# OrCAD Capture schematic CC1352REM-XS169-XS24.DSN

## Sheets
1 Mechanical: size A4; title: CC1352REM-XS169-XS24; rev: C0
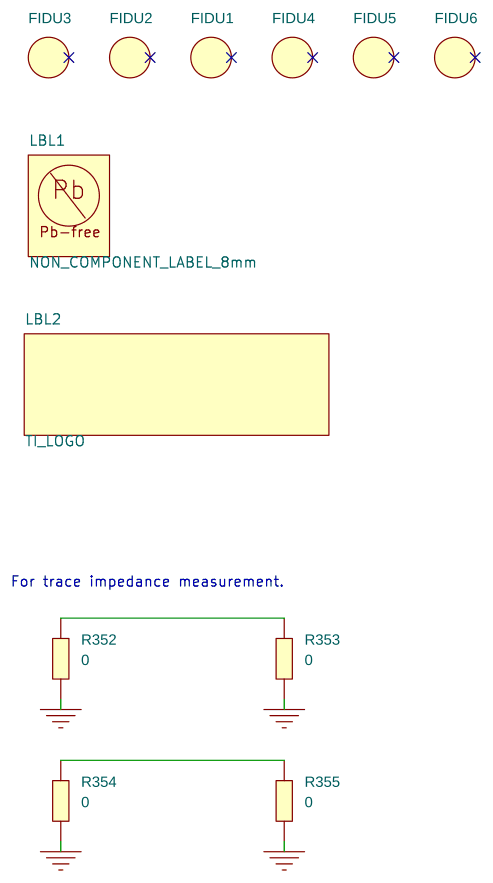
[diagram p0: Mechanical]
2 CC1352REM-XS169-XS24: size A3
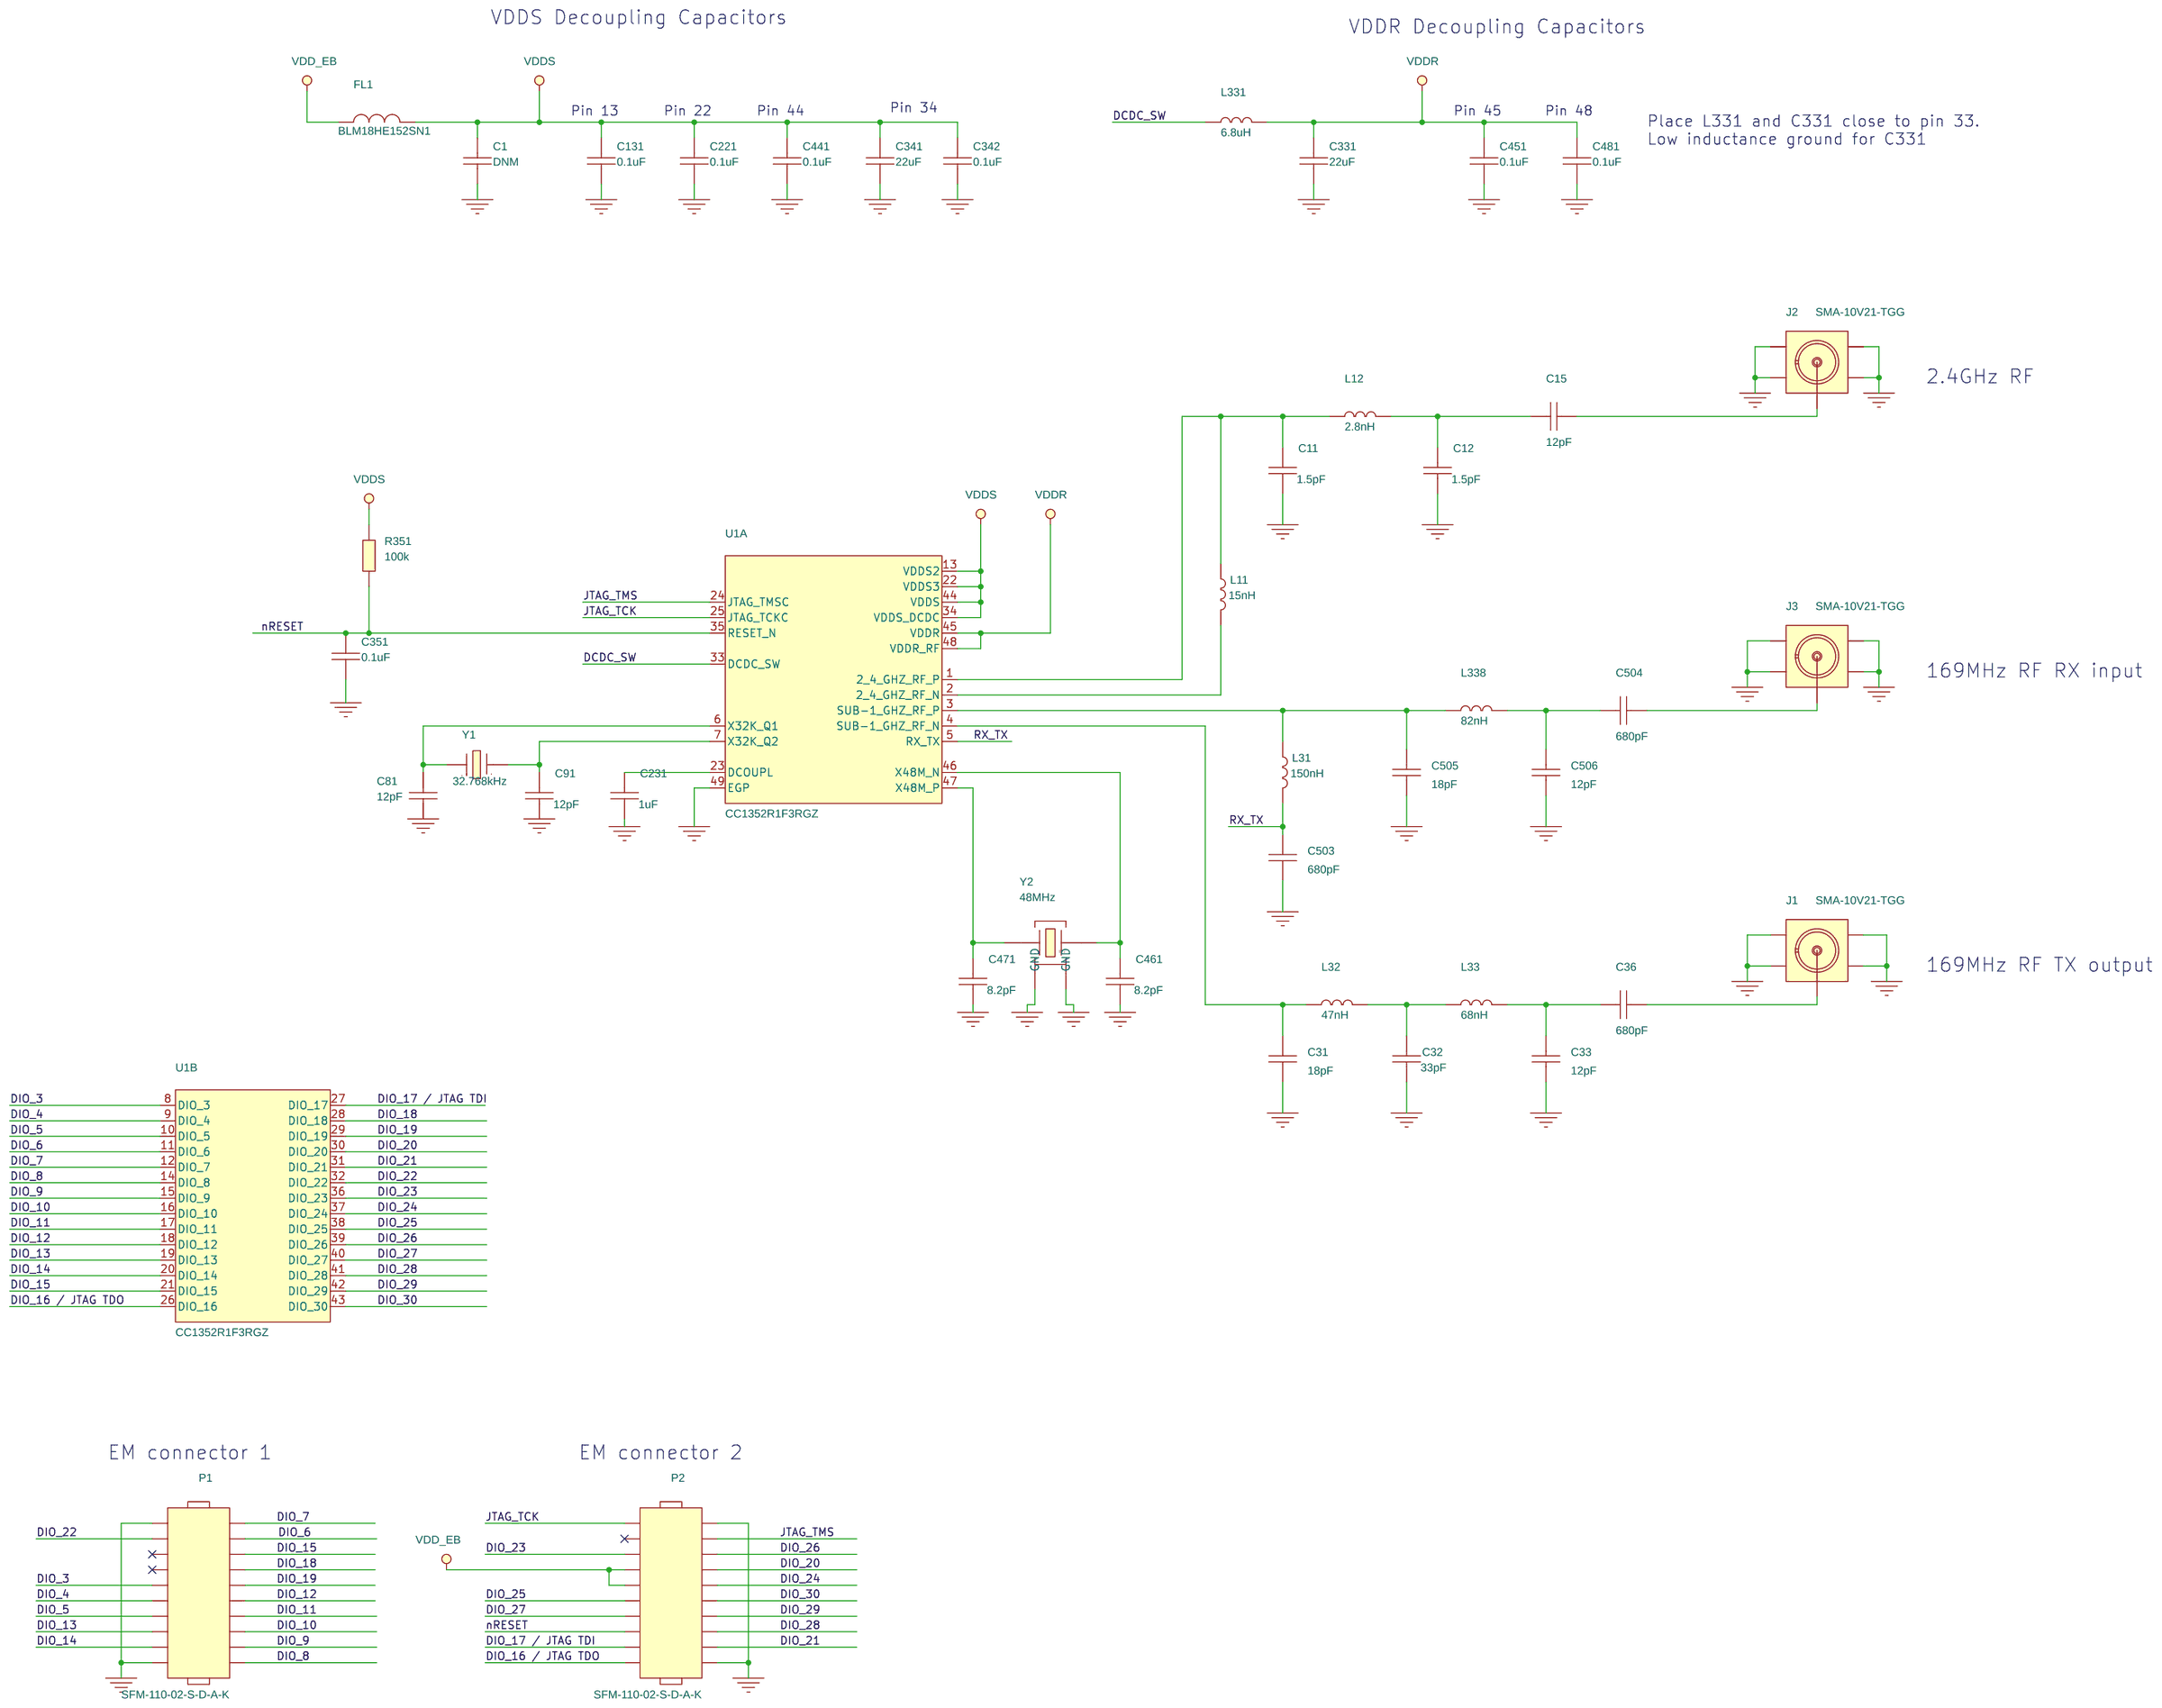
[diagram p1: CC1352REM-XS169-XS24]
3 Revision
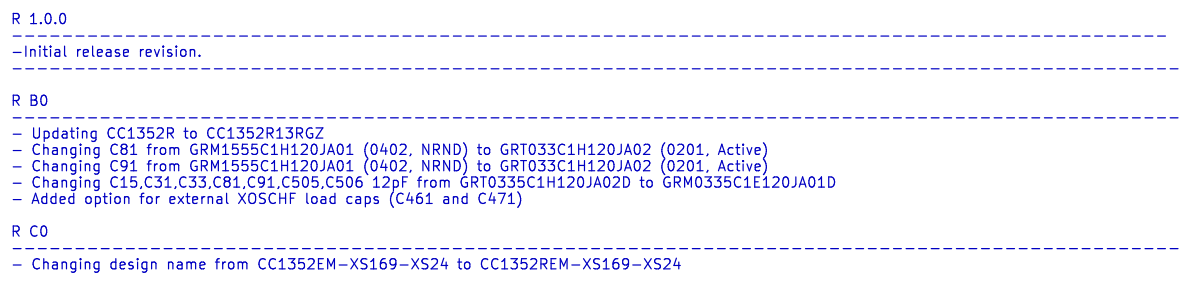
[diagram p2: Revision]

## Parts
sheet CC1352REM-XS169-XS24
C1  DNM  [CAPC1608X90A2N]
C11  1.5pF  [CAPC0603X35B2N]
C12  1.5pF  [CAPC0603X35B2N]
C15  12pF  [CAPC0603X35B2N]
C31  18pF  [CAPC0603X35B2N]
C32  33pF  [CAPC0603X35B2N]
C33  12pF  [CAPC0603X35B2N]
C36  680pF  [CAPC0603X35B2N]
C81  12pF  [CAPC0603X35B2N]
C91  12pF  [CAPC0603X35B2N]
C131  0.1uF  [CAPC1005X60B2N]
C221  0.1uF  [CAPC1005X60B2N]
C231  1uF  [CAPC1005X60A2N]
C331  22uF  [CAPC1608X100A2N]
C341  22uF  [CAPC1608X100A2N]
C342  0.1uF  [CAPC1005X60B2N]
C351  0.1uF  [CAPC1005X60B2N]
C441  0.1uF  [CAPC1005X60B2N]
C451  0.1uF  [CAPC1005X60B2N]
C461  8.2pF  [CAPC0603X35B2N]
C471  8.2pF  [CAPC0603X35B2N]
C481  0.1uF  [CAPC1005X60B2N]
C503  680pF  [CAPC0603X35B2N]
C504  680pF  [CAPC0603X35B2N]
C505  18pF  [CAPC0603X35B2N]
C506  12pF  [CAPC0603X35B2N]
FL1  BLM18HE152SN1  [FIL_BLM18HE152SN1DN]
J1  SMA-10V21-TGG  [HUSTSAN_SMA10V21TGGAN]
J2  SMA-10V21-TGG  [HUSTSAN_SMA10V21TGGAN]
J3  SMA-10V21-TGG  [HUSTSAN_SMA10V21TGGAN]
L11  15nH  [INDC0603X33A2N]
L12  2.8nH  [INDC0603X33A2N]
L31  150nH  [INDC0603X33A2N]
L32  47nH  [INDC1005X60B2N]
L33  68nH  [INDC1005X60A2N]
L331  6.8uH  [INDC2012X150A2N]
L338  82nH  [INDC1005X60A2N]
P1  SFM-110-02-S-D-A-K  [SAMTEC_SFM11002AN]
P2  SFM-110-02-S-D-A-K  [SAMTEC_SFM11002AN]
R351  100k  [RESC1005X40B2N]
U1  CC1352R1F3RGZ  [QFNFC50P700X700X100-49A2N]  (sections A,B)
Y1  32.768kHz  [XTAL_FC135_A2N]
Y2  48MHz  [OSCCC200X160X50-4B2N]
sheet Mechanical
FIDU1  FIDU_1MM  [FID100X115B]
FIDU2  FIDU_1MM  [FID100X115B]
FIDU3  FIDU_1MM  [FID100X115B]
FIDU4  FIDU_1MM  [FID100X115B]
FIDU5  FIDU_1MM  [FID100X115B]
FIDU6  FIDU_1MM  [FID100X115B]
LBL1  NON_COMPONENT_LABEL_8mm  [LABEL_PB-FREE_8MM_A2N]
LBL2  TI_LOGO  [TI_LOGO_1]
R352  0  [RESC0603X35B2N]
R353  0  [RESC0603X35B2N]
R354  0  [RESC0603X35B2N]
R355  0  [RESC0603X35B2N]

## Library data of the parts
C1 = CAPACITOR: CAPACITOR, CERAMIC, TBD, 0603, SMD, DNM; ALT_SYMBOLS: CAPC1608X90A2L,CAPC1608X90A2M; Additional Datasheet URL: N/A; AutoDoc File: https://notefied-dynamic-precision.com/DB/Apps/Desktop/Item/Object.aspx?id=50475; BU Name: DYNAMIC PRECISION GDANSK; Client Status: RELEASED; Country of Origin: Missing Info; Datasheet URL: N/A; Datasheet URL 1: N/A; Datasheet URL 2: N/A; Mass: N/A; Max Oper Temp: N/A; Maximum Operating Temperature: N/A; Min Oper Temp: N/A; Minimum Operating Temperature: N/A; Mounting Type: SMD; NOTEfied URL: https://notefied-dynamic-precision.com/NOTEfiedWebInterface/part/show?partNumber=02-01324; Old Footprint: CAPC1608X90N,0603; PCB Package: 0603; Packing Size: N/A; Packing Type: Missing Info; Part Number: 02-01324; Part Type: Capacitor|CERAMIC|0603|STANDARD; ROHS: Compliant; Revision: R024; RoHS Status: ROHS_COMPLIANT; Status: Released; Type: Capacitor; Vendor: MANUFACTURER SELECTION; Vendor Part Number: CAPACITOR_TBD_0603_DNM; Vendor Part Status: Active; Weight: N/A
C11 C12 = CAPACITOR: CAPACITOR, CERAMIC C0G/NP0, 1.5pF, 50V, -0.1pF/+0.1pF, -55DEGC/+125DEGC, 0201, SMD; ALT_SYMBOLS: CAPC0603X35B2L,CAPC0603X35B2M; Additional Datasheet URL: https://search.murata.co.jp/Ceramy/image/img/A01X/G101/ENG/GRM0335C1H1R5BA01-01A.pdf; Budgetary Price: 0.00272 USD; Country of Origin: Missing Info; Datasheet URL: https://www.murata.com/-/media/webrenewal/support/library/catalog/products/capacitor/mlcc/c02e.ashx?la=en-gb; Dielectric Type: C0G/NP0; Lead Time: 11; Mass: 0.00033g; Maximum Operating Temperature: +125DEGC; Maximum Tolerance: +0.1pF; Minimum Operating Temperature: -55DEGC; Minimum Tolerance: -0.1pF; Mounting Type: SMD; NOTEfied URL: https://notefied-dynamic-precision.com/NOTEfiedWebInterface/part/show?partNumber=02-06129; PCB Package: 0201; Packing Size: 50000; Packing Type: Tape & Reel; Part Number: 02-06129; Part Type: Capacitor|CERAMIC|0201|STANDARD; REACH/SVHC Compliance: Compliant; REACH/SVHC Details: SVHC List Version Jul 7, 2017; REACH/SVHC Source: REACH Declaration; REACH/SVHC Status: Unaffected; ROHS: Compliant; Rated Voltage: 50V; Revision: R020; Status: Released; Texas Part Status: Under Review; Type: Capacitor; Vendor: MURATA; Vendor Part Number: GRM0335C1H1R5BA01J; Vendor Part Status: Active
C15 C33 C506 = CAPACITOR: CAPACITOR, CERAMIC C0G/NP0, 12pF, 25V, -5%/+5%, -55DEGC/+125DEGC, 0201, SMD; ALT_SYMBOLS: CAPC0603X35B2L,CAPC0603X35B2M; Additional Datasheet URL: https://www.murata.com/-/media/webrenewal/support/library/catalog/products/capacitor/mlcc/c02e.ashx?la=en-gb; Datasheet URL: https://search.murata.co.jp/Ceramy/image/img/A01X/G101/ENG/GRM0335C1E120JA01-01A.pdf; Dielectric Type: C0G/NP0; Mass: 0.00033g; Maximum Operating Temperature: +125DEGC; Maximum Tolerance: +5%; Minimum Operating Temperature: -55DEGC; Minimum Tolerance: -5%; Mounting Type: SMD; NOTEfied URL: https://notefied-dynamic-precision.com/NOTEfiedWebInterface/part/show?partNumber=02-09489; PCB Package: 0201; Packing Size: 15000; Packing Type: Tape & Reel; Part Number: 02-09489; Part Type: Capacitor|CERAMIC|0201|STANDARD; REACH/SVHC Compliance: Compliant; REACH/SVHC Details: SVHC List Version Jul 16, 2019; REACH/SVHC Source: REACH Declaration; REACH/SVHC Status: Unaffected; ROHS: Compliant; Rated Voltage: 25V; Revision: R001; Status: Released; Texas Part Status: Under Review; Type: Capacitor; Vendor: MURATA; Vendor Part Number: GRM0335C1E120JA01D; Vendor Part Status: Active
C31 C505 = CAPACITOR: CAPACITOR, CERAMIC C0G/NP0, 18pF, 25V, -5%/+5%, -55DEGC/+125DEGC, 0201, SMD; ALT_SYMBOLS: CAPC0603X35B2L,CAPC0603X35B2M; Additional Datasheet URL: https://search.murata.co.jp/Ceramy/image/img/A01X/G101/ENG/GRM0335C1E180JA01-01A.pdf; Budgetary Price: 0.0024 USD; Datasheet URL: https://www.murata.com/-/media/webrenewal/support/library/catalog/products/capacitor/mlcc/c02e.ashx?la=en-gb; Dielectric Type: C0G/NP0; Lead Time: 11; Mass: 0.00033g; Maximum Operating Temperature: +125DEGC; Maximum Tolerance: +5%; Minimum Operating Temperature: -55DEGC; Minimum Tolerance: -5%; Mounting Type: SMD; NOTEfied URL: https://notefied-dynamic-precision.com/NOTEfiedWebInterface/part/show?partNumber=02-09247; PCB Package: 0201; Packing Size: 15000; Packing Type: Tape & Reel; Part Number: 02-09247; Part Type: Capacitor|CERAMIC|0201|STANDARD; REACH/SVHC Compliance: Compliant; REACH/SVHC Details: SVHC List Version Jan 16, 2020; REACH/SVHC Source: REACH Declaration; REACH/SVHC Status: Unaffected; ROHS: Compliant; Rated Voltage: 25V; Revision: R004; Status: Released; Texas Part Status: Under Review; Type: Capacitor; Vendor: MURATA; Vendor Part Number: GRM0335C1E180JA01D; Vendor Part Status: Active
C32 = CAPACITOR: CAPACITOR, CERAMIC, C0G/NP0, 33pF, 25V, -5%/+5%, -55DEGC/+125DEGC, 0201, SMD; ALT_SYMBOLS: CAPC0603X35B2L,CAPC0603X35B2M; Additional Datasheet URL: https://search.murata.co.jp/Ceramy/image/img/A01X/G101/ENG/GRM0335C1E330JA01-01A.pdf; Budgetary Price: 0.0024 USD; Datasheet URL: https://www.murata.com/-/media/webrenewal/support/library/catalog/products/capacitor/mlcc/c02e.ashx?la=en-gb; Dielectric Type: C0G/NP0; Lead Time: 11; Mass: 0.00033g; Maximum Operating Temperature: +125DEGC; Maximum Tolerance: +5%; Minimum Operating Temperature: -55DEGC; Minimum Tolerance: -5%; Mounting Type: SMD; NOTEfied URL: https://notefied-dynamic-precision.com/NOTEfiedWebInterface/part/show?partNumber=02-08392; PCB Package: 0201; Packing Size: 15000; Packing Type: Tape & Reel; Part Number: 02-08392; Part Type: Capacitor|CERAMIC|0201|STANDARD; ROHS: Compliant; Rated Voltage: 25V; Revision: R005; Status: Released; Type: Capacitor; Vendor: MURATA; Vendor Part Number: GRM0335C1E330JA01D; Vendor Part Status: Active
C36 C503 C504 = CAPACITOR: CAPACITOR, CERAMIC, C0G/NP0, 680pF, 25V, -5%/+5%, -55DEGC/+125DEGC, 0201, SMD; ALT_SYMBOLS: CAPC0603X35B2L,CAPC0603X35B2M; Additional Datasheet URL: https://search.murata.co.jp/Ceramy/image/img/A01X/G101/ENG/GRM0335C1E681JA01-01A.pdf; Datasheet URL: https://www.murata.com/-/media/webrenewal/support/library/catalog/products/capacitor/mlcc/c02e.ashx?la=en-gb; Dielectric Type: C0G/NP0; Mass: 0.00033g; Maximum Operating Temperature: +125DEGC; Maximum Tolerance: +5%; Minimum Operating Temperature: -55DEGC; Minimum Tolerance: -5%; Mounting Type: SMD; NOTEfied URL: https://notefied-dynamic-precision.com/NOTEfiedWebInterface/part/show?partNumber=02-09578; PCB Package: 0201; Packing Size: 15000; Packing Type: Tape & Reel; Part Number: 02-09578; Part Type: Capacitor|CERAMIC|0201|STANDARD; REACH/SVHC Compliance: Compliant; REACH/SVHC Details: SVHC List Version Jan 16, 2020; REACH/SVHC Source: REACH Declaration; REACH/SVHC Status: Unaffected; ROHS: Compliant; Rated Voltage: 25V; Revision: R001; Status: Released; Texas Part Status: Under Review; Type: Capacitor; Vendor: MURATA; Vendor Part Number: GRM0335C1E681JA01D; Vendor Part Status: Active
C81 = CAPACITOR: CAPACITOR, CERAMIC C0G/NP0, 12pF, 25V, -5%/+5%, -55DEGC/+125DEGC, 0201, SMD; ALT_SYMBOLS: CAPC0603X35B2L,CAPC0603X35B2M; Additional Datasheet URL: https://www.murata.com/-/media/webrenewal/support/library/catalog/products/capacitor/mlcc/c02e.ashx?la=en-gb; AutoDoc File: https://notefied-dynamic-precision.com/DB/Apps/Desktop/Item/Object.aspx?id=113345; BU Name: TEXAS INSTRUMENTS NORWAY; Budget Currency: EUR; Budget Price: 0.007; Datasheet URL: https://search.murata.co.jp/Ceramy/image/img/A01X/G101/ENG/GRM0335C1E120JA01-01A.pdf; Datasheet URL 1: http://psearch.murata.com/capacitor/product/GRM1555C1H120JA01%23.pdf; Datasheet URL 2: http://search.murata.co.jp/Ceramy/image/img/w_hinm/L0005E.pdf; Definied Quality: INDUSTRIAL; Dielectric Type: C0G/NP0; Esd Level: N/A; MPN: GRM1555C1H120JA01D; MPN Status: ACTIVE; MSL: 1; MTBF: N/A; MTBF Standard: N/A; Manufacturer: MURATA; Mass: 0.00033g; Max Oper Temp: +125DEGC; Max Tol: +5%; Maximum Operating Temperature: +125DEGC; Maximum Tolerance: +5%; Min Oper Temp: -55DEGC; Min Tol: -5%; Minimum Operating Temperature: -55DEGC; Minimum Tolerance: -5%; Mounting Type: SMD; NOTE Status: PREFERRED; NOTEfied URL: https://notefied-dynamic-precision.com/NOTEfiedWebInterface/part/show?partNumber=02-09489; Old Footprint: CAPC1005X60N; PCB Package: 0201; Packing Size: 15000; Packing Type: Tape & Reel; Part Number: 02-09489; Part Type: Capacitor|CERAMIC|0201|STANDARD; REACH/SVHC Compliance: Compliant; REACH/SVHC Details: SVHC List Version Jul 16, 2019; REACH/SVHC Source: REACH Declaration; REACH/SVHC Status: Unaffected; REACH/SVHC_COMPLIANCE: COMPLIANT; REACH/SVHC_DETAILS: SVHC LIST VERSION Dec 17, 2015; REACH/SVHC_SOURCE: REACH DECLARATION; REACH/SVHC_STATUS: UNAFFECTED; ROHS: Compliant; Rated Voltage: 25V; Revision: R001; RoHS Status: ROHS_COMPLIANT; Rtd Voltage: 50V; Status: Released; Texas Part Status: Under Review; Type: Capacitor; Vendor: MURATA; Vendor Part Number: GRM0335C1E120JA01D; Vendor Part Status: Active; WEIGHT: 0.0016g
C91 = CAPACITOR: CAPACITOR, CERAMIC C0G/NP0, 12pF, 25V, -5%/+5%, -55DEGC/+125DEGC, 0201, SMD; ALT_SYMBOLS: CAPC0603X35B2L,CAPC0603X35B2M; Additional Datasheet URL: https://www.murata.com/-/media/webrenewal/support/library/catalog/products/capacitor/mlcc/c02e.ashx?la=en-gb; AutoDoc File: https://notefied-dynamic-precision.com/DB/Apps/Desktop/Item/Object.aspx?id=114571; BU Name: TEXAS INSTRUMENTS NORWAY; Budget Currency: EUR; Budget Price: 0.006; Client Status: UNDER_REVIEW; Datasheet URL: https://search.murata.co.jp/Ceramy/image/img/A01X/G101/ENG/GRM0335C1E120JA01-01A.pdf; Datasheet URL 1: http://psearch.murata.com/capacitor/product/GRM1555C1H150JA01%23.pdf; Datasheet URL 2: http://psearch.en.murata.com/capacitor/product/GRM1555C1H150JA01%23.html; Definied Quality: INDUSTRIAL; Dielectric Type: C0G/NP0; Esd Level: N/A; LifeCycle Status: ACTIVE; MPN: CAPACITOR_0402_12pF_C0G/NP0_M_+/-5%_50V; MPN Status: ACTIVE; MSL: N/A; MTBF: N/A; MTBF Standard: N/A; Manufacturer: MANUFACTURER SELECTION; Mass: 0.00033g; Max Oper Temp: +125DEGC; Max Tol: +5%; Maximum Operating Temperature: +125DEGC; Maximum Tolerance: +5%; Min Oper Temp: -55DEGC; Min Tol: -5%; Minimum Operating Temperature: -55DEGC; Minimum Tolerance: -5%; Mounting Type: SMD; NOTE Status: PREFERRED; NOTEfied URL: https://notefied-dynamic-precision.com/NOTEfiedWebInterface/part/show?partNumber=02-09489; Old Footprint: CAPC1005X60N; PCB Package: 0201; Packing Size: 15000; Packing Type: Tape & Reel; Part Number: 02-09489; Part Type: Capacitor|CERAMIC|0201|STANDARD; REACH/SVHC Compliance: Compliant; REACH/SVHC Details: SVHC List Version Jul 16, 2019; REACH/SVHC Source: REACH Declaration; REACH/SVHC Status: Unaffected; REACH/SVHC_COMPLIANCE: COMPLIANT; REACH/SVHC_DETAILS: SVHC List Version Jan 12, 2017; REACH/SVHC_SOURCE: REACH DECLARATION; REACH/SVHC_STATUS: UNAFFECTED; ROHS: Compliant; Rated Voltage: 25V; Revision: R001; RoHS Status: ROHS_COMPLIANT; Rtd Voltage: 50V; Status: Released; Texas Part Status: Under Review; Type: Capacitor; Vendor: MURATA; Vendor Part Number: GRM0335C1E120JA01D; Vendor Part Status: Active; WEIGHT: 0.0016g
C131 C221 C351 C441 C451 C481 = CAPACITOR: CAPACITOR, CERAMIC X7R, 0.1uF, 25V, -10%/+10%, -55DEGC/+125DEGC, 0402, SMD; Additional Datasheet URL: https://search.murata.co.jp/Ceramy/image/img/A01X/G101/ENG/GRM155R71E104KE14-01A.pdf; AutoDoc File: https://notefied-dynamic-precision.com/DB/Apps/Desktop/Item/Object.aspx?id=115293; BU Name: TEXAS INSTRUMENTS NORWAY; Budgetary Price: 0.00567 USD; Client Status: UNDER_REVIEW; Datasheet URL: https://www.murata.com/-/media/webrenewal/support/library/catalog/products/capacitor/mlcc/c02e.ashx?la=en-gb; Datasheet URL 1: http://psearch.en.murata.com/capacitor/product/GRM155R71E104KE14%23.pdf; Datasheet URL 2: http://search.murata.co.jp/Ceramy/image/img/w_hinm/L0005E.pdf; Dielectric Type: X7R; Lead Time: 11; LifeCycle Status: ACTIVE; MPN: GRM155R70J104KA01D; MPN Status: ACTIVE; Manufacturer: MURATA; Mass: 0.0016g; Max Oper Temp: +125DEGC; Max Tol: +10%; Maximum Operating Temperature: +125DEGC; Maximum Tolerance: +10%; Min Oper Temp: -55DEGC; Min Tol: -10%; Minimum Operating Temperature: -55DEGC; Minimum Tolerance: -10%; Mounting Type: SMD; NOTE Status: PREFERRED; NOTEfied URL: https://notefied-dynamic-precision.com/NOTEfiedWebInterface/part/show?partNumber=02-07861; Old Footprint: CAPC1005X60N,0402; PCB Package: 0402; Packing Size: 10000; Packing Type: Tape & Reel; Part Number: 02-07861; Part Type: Capacitor|CERAMIC|0402|STANDARD; REACH/SVHC Compliance: Compliant; REACH/SVHC Details: SVHC List Version Jul 7, 2017; REACH/SVHC Source: REACH Declaration; REACH/SVHC Status: Unaffected; REACH/SVHC_COMPLIANCE: COMPLIANT; REACH/SVHC_DETAILS: SVHC LIST VERSION Jun 20, 2016; REACH/SVHC_SOURCE: REACH DECLARATION; REACH/SVHC_STATUS: UNAFFECTED; ROHS: Compliant; Rated Voltage: 25V; Revision: R017; RoHS Status: ROHS_COMPLIANT; Rtd Voltage: 25V; Status: Released; Texas Part Status: Under Review; Type: Capacitor; Vendor: MURATA; Vendor Part Number: GRM155R71E104KE14D; Vendor Part Status: Active; WEIGHT: 0.0016g
C231 = CAPACITOR: CAPACITOR, CERAMIC X5R, 1uF, 25V, -10%/+10%, -55DEGC/+85DEGC, 0402, SMD; ALT_SYMBOLS: CAPC1005X60A2L,CAPC1005X60A2M; Additional Datasheet URL: https://search.murata.co.jp/Ceramy/image/img/A01X/G101/ENG/GRM155R61E105KA12-01A.pdf; Budgetary Price: 0.01386 USD; Country of Origin: China,Philippines; Datasheet URL: https://www.murata.com/-/media/webrenewal/support/library/catalog/products/capacitor/mlcc/c02e.ashx?la=en-gb; Dielectric Type: X5R; FPLIST: CAPC1005X60A2N,CAPC1005X60B2N; Lead Time: 11; Mass: 0.0016g; Maximum Operating Temperature: +85DEGC; Maximum Tolerance: +10%; Minimum Operating Temperature: -55DEGC; Minimum Tolerance: -10%; Mounting Type: SMD; NOTEfied URL: https://notefied-dynamic-precision.com/NOTEfiedWebInterface/part/show?partNumber=02-07864; PCB Package: 0402; Packing Size: 10000; Packing Type: Tape & Reel; Part Number: 02-07864; Part Type: Capacitor|CERAMIC|0402|STANDARD; REACH/SVHC Compliance: Compliant; REACH/SVHC Details: SVHC List Version Jan 15, 2018; REACH/SVHC Source: REACH Declaration; REACH/SVHC Status: Unaffected; ROHS: Compliant; Rated Voltage: 25V; Revision: R024; Status: Released; Texas Part Status: Under Review; Type: Capacitor; Vendor: MURATA; Vendor Part Number: GRM155R61E105KA12D; Vendor Part Status: Active
C331 C341 = CAPACITOR: CAPACITOR, CERAMIC, X5R, 22uF, 6.3V, -20%/+20%, -55DEGC/+85DEGC, 0603, SMD; ALT_SYMBOLS: CAPC1608X100A2L,CAPC1608X100A2M; Additional Datasheet URL: https://search.murata.co.jp/Ceramy/image/img/A01X/G101/ENG/GRM188R60J226MEA0-01A.pdf; AutoDoc File: https://notefied-dynamic-precision.com/DB/Apps/Desktop/Item/Object.aspx?id=104385; BU Name: DYNAMIC PRECISION GDANSK; Budget Currency: EUR; Budget Price: 0.062; Budgetary Price: 0.04731 USD; Client Status: UNDER_REVIEW; Country of Origin: Japan; Datasheet URL: https://www.murata.com/-/media/webrenewal/support/library/catalog/products/capacitor/mlcc/c02e.ashx?la=en-gb; Datasheet URL 1: http://psearch.murata.com/capacitor/product/GRM188R60J226MEA0%23.pdf; Datasheet URL 2: http://search.murata.co.jp/Ceramy/image/img/w_hinm/L0005E.pdf; Definied Quality: INDUSTRIAL; Dielectric Type: X5R; Esd Level: N/A; Lead Time: 11; LifeCycle Status: ACTIVE; MPN: GRM188R60J226MEA0D; MPN Status: ACTIVE; Manufacturer: MURATA; Mass: 0.0091g; Max Oper Temp: +85DEGC; Max Tol: +20%; Maximum Operating Temperature: +85DEGC; Maximum Tolerance: +20%; Min Oper Temp: -55DEGC; Min Tol: -20%; Minimum Operating Temperature: -55DEGC; Minimum Tolerance: -20%; Mounting Type: SMD; NOTE Status: PREFERRED; NOTEfied URL: https://notefied-dynamic-precision.com/NOTEfiedWebInterface/part/show?partNumber=02-07053; PCB Package: 0603; Packing Size: 4000; Packing Type: Tape & Reel; Part Number: 02-07053; Part Type: Capacitor|CERAMIC|0603|STANDARD; REACH/SVHC Compliance: Compliant; REACH/SVHC Details: SVHC List Version Jul 7, 2017; REACH/SVHC Source: REACH Declaration; REACH/SVHC Status: Unaffected; REACH/SVHC_COMPLIANCE: COMPLIANT; REACH/SVHC_DETAILS: SVHC LIST VERSION Dec 17, 2015; REACH/SVHC_SOURCE: REACH DECLARATION; REACH/SVHC_STATUS: UNAFFECTED; ROHS: Compliant; Rated Voltage: 6.3V; Revision: R018; RoHS Status: ROHS_COMPLIANT; Rtd Voltage: 6.3V; Status: Released; Texas Part Status: Under Review; Type: Capacitor; Vendor: MURATA; Vendor Part Number: GRM188R60J226MEA0D; Vendor Part Status: Active; WEIGHT: 0.0091g
C342 = CAPACITOR: CAPACITOR, CERAMIC X7R, 0.1uF, 25V, -10%/+10%, -55DEGC/+125DEGC, 0402, SMD; Additional Datasheet URL: https://search.murata.co.jp/Ceramy/image/img/A01X/G101/ENG/GRM155R71E104KE14-01A.pdf; AutoDoc File: https://notefied-dynamic-precision.com/DB/Apps/Desktop/Item/Object.aspx?id=115293; BU Name: TEXAS INSTRUMENTS NORWAY; Budgetary Price: 0.00567 USD; Cage Code: C0151; Client Status: UNDER_REVIEW; Datasheet URL: https://www.murata.com/-/media/webrenewal/support/library/catalog/products/capacitor/mlcc/c02e.ashx?la=en-gb; Datasheet URL 1: http://psearch.en.murata.com/capacitor/product/GRM155R71E104KE14%23.pdf; Datasheet URL 2: http://search.murata.co.jp/Ceramy/image/img/w_hinm/L0005E.pdf; Definied Quality: INDUSTRIAL; Dielectric Type: X7R; Esd Level: N/A; Lead Time: 11; MPN: GRM188R71E104KA01D; MPN Status: NRND; MSL: 1; MTBF: N/A; MTBF Standard: N/A; Manufacturer: MURATA; Mass: 0.0016g; Max Oper Temp: +125DEGC; Max Tol: +10%; Maximum Operating Temperature: +125DEGC; Maximum Tolerance: +10%; Min Oper Temp: -55DEGC; Min Tol: -10%; Minimum Operating Temperature: -55DEGC; Minimum Tolerance: -10%; Mounting Type: SMD; NOTE Status: PREFERRED; NOTEfied URL: https://notefied-dynamic-precision.com/NOTEfiedWebInterface/part/show?partNumber=02-07861; Old Footprint: CAPC1608X90N,0603; PCB Package: 0402; Packing Size: 10000; Packing Type: Tape & Reel; Part Number: 02-07861; Part Type: Capacitor|CERAMIC|0402|STANDARD; REACH/SVHC Compliance: Compliant; REACH/SVHC Details: SVHC List Version Jul 7, 2017; REACH/SVHC Source: REACH Declaration; REACH/SVHC Status: Unaffected; REACH/SVHC_COMPLIANCE: COMPLIANT; REACH/SVHC_DETAILS: SVHC LIST VERSION Jun 20, 2016; REACH/SVHC_SOURCE: REACH DECLARATION; REACH/SVHC_STATUS: UNAFFECTED; ROHS: Compliant; Rated Voltage: 25V; Revision: R017; RoHS Status: ROHS_COMPLIANT; Rtd Voltage: 25V; Status: Released; Texas Part Status: Under Review; Type: Capacitor; Vendor: MURATA; Vendor Part Number: GRM155R71E104KE14D; Vendor Part Status: Active; WEIGHT: 0.0016g
C461 C471 = CAPACITOR: CAPACITOR, CERAMIC, C0G/NP0, 8.2pF, 25V, -0.25pF/+0.25pF, -55DEGC/+125DEGC, 0201, SMD; ALT_SYMBOLS: CAPC0603X35B2L,CAPC0603X35B2M; Additional Datasheet URL: https://search.murata.co.jp/Ceramy/image/img/A01X/G101/ENG/GRM0335C1E8R2CA01-01A.pdf; Budgetary Price: 0.0024 USD; Datasheet URL: https://www.murata.com/-/media/webrenewal/support/library/catalog/products/capacitor/mlcc/c02e.ashx?la=en-gb; Dielectric Type: C0G/NP0; Lead Time: 11; Mass: 0.00033g; Maximum Operating Temperature: +125DEGC; Maximum Tolerance: +0.25pF; Minimum Operating Temperature: -55DEGC; Minimum Tolerance: -0.25pF; Mounting Type: SMD; NOTEfied URL: https://notefied-dynamic-precision.com/NOTEfiedWebInterface/part/show?partNumber=02-08393; PCB Package: 0201; Packing Size: 15000; Packing Type: Tape & Reel; Part Number: 02-08393; Part Type: Capacitor|CERAMIC|0201|STANDARD; ROHS: Compliant; Rated Voltage: 25V; Revision: R005; Status: Released; Type: Capacitor; Vendor: MURATA; Vendor Part Number: GRM0335C1E8R2CA01D; Vendor Part Status: Active
FL1 = FILTER_2PIN: FILTER, EMI, FERRITE BEAD, 1500@100MHz, -25%/+25%, -55DEGC/+125DEGC, 0603, SMD; ALT_SYMBOLS: FIL_BLM18HE152SN1DL,FIL_BLM18HE152SN1DM; Additional Datasheet URL: https://www.murata.com/en-eu/products/productdata/8796741599262/ENFA0004.pdf?1531144803000; AutoDoc File: https://notefied-dynamic-precision.com/DB/Apps/Desktop/Item/Object.aspx?id=85575; BU Name: DYNAMIC PRECISION GDANSK; Budget Currency: EUR; Budget Price: 0.065; Budgetary Price: 0.07 EUR; CLASS: IC; Client Status: UNDER_REVIEW; Country of Origin: Japan,Singapore,Thailand; Datasheet URL: https://www.murata.com/~/media/webrenewal/support/library/catalog/products/emc/emifil/c31e.ashx; Datasheet URL 1: http://search.murata.co.jp/Ceramy/image/img/PDF/ENG/L0110S0101BLM18H.pdf; Datasheet URL 2: http://search.murata.co.jp/Ceramy/image/img/w_hinm/L0110E.pdf; Frequency: 100MHz; Impedance: 1500; Inductance: N/A; Lead Time: 8; MPN: BLM18HE152SN1D; MPN Status: ACTIVE; Manufacturer: MURATA; Mass: 0.006g; Max Oper Temp: +125DEGC; Max Tol: +25%; Maximum Operating Temperature: +125DEGC; Maximum Tolerance: +25%; Min Oper Temp: -55DEGC; Min Tol: -25%; Minimum Operating Temperature: -55DEGC; Minimum Tolerance: -25%; Mounting Type: SMD; NOTE Status: PREFERRED; NOTEfied URL: https://notefied-dynamic-precision.com/NOTEfiedWebInterface/part/show?partNumber=04-00470; PCB Package: 0603; Packing Size: 4000; Packing Type: Tape & Reel; Part Number: 04-00470; Part Type: Filter|EMI|FERRITE BEAD|0603; REACH/SVHC Compliance: Compliant; REACH/SVHC Details: SVHC List Version Jul 7, 2017; REACH/SVHC Source: REACH Declaration; REACH/SVHC Status: Unaffected; REACH/SVHC_COMPLIANCE: COMPLIANT; REACH/SVHC_DETAILS: SVHC LIST VERSION Dec 17, 2015; REACH/SVHC_SOURCE: REACH DECLARATION; REACH/SVHC_STATUS: UNAFFECTED; ROHS: Compliant; Rated Current: 0.5A; Rated Voltage: N/A; Revision: R017; RoHS Status: ROHS_COMPLIANT; Rtd Current: 0.5A; Rtd Voltage: N/A; Status: Released; Texas Part Status: Under Review; Type: Filter; Vendor: MURATA; Vendor Part Number: BLM18HE152SN1D; Vendor Part Status: Active; WEIGHT: 0.006g
J1-J3 = CONN_COAX_1+4: CONNECTOR, COAX, RF, FEMALE, STRAIGHT, 1 PIN, SMD; ALT_SYMBOLS: HUSTSAN_SMA10V21TGGL,HUSTSAN_SMA10V21TGGM; Additional Datasheet URL: http://www.hustsan.com.tw/cgi-bin/productfn/pdt_detail_lst.pl?ProdID=143; AutoDoc File: https://notefied-dynamic-precision.com/DB/Apps/Desktop/Item/Object.aspx?id=84956; BU Name: DYNAMIC PRECISION GDANSK; Budget Currency: N/A; Budget Price: N/A; CLASS: IO; Client Status: UNDER_REVIEW; Country of Origin: Taiwan; Datasheet URL: http://www.hustsan.com.tw/uploaddir/product/SMA-10V21.pdf; Datasheet URL 1: http://www.hustsan.com.tw/uploaddir/product/SMA-10V21.pdf; Datasheet URL 2: http://www.hustsan.com.tw/cgi-bin/productfn/pdt_detail_lst.pl?ProdID=143; FPLIST: HUSTSAN_SMA10V21TGGAN,HUSTSAN_SMA10V21TGGN; MPN Status: ACTIVE; MSL: N/A; Manufacturer: HUS-TSAN; Mass: N/A; Mounting Type: SMD; NOTE Status: PREFERRED; NOTEfied URL: https://notefied-dynamic-precision.com/NOTEfiedWebInterface/part/show?partNumber=06-02188; No Of Pos: 1; Number of Positions: 1; Old Footprint: HUSTSAN_SMA10V21TGGAN,HUSTSAN_SMA10V21TGGN; Packing Size: 350; Packing Type: Tape & Reel; Part Number: 06-02188; Part Type: Connector|COAX|RF; REACH/SVHC Compliance: Compliant; REACH/SVHC Details: SVHC List Version Jun 20, 2016; REACH/SVHC Source: REACH Declaration; REACH/SVHC Status: Unaffected; ROHS: Compliant; Revision: R018; RoHS Status: ROHS_COMPLIANT; Status: Released; Texas Part Status: Under Review; Type: Connector; Vendor: HUS-TSAN; Vendor Part Status: Active; WEIGHT: N/A
L11 = INDUCTOR: INDUCTOR, RF, CHIP, NON-MAGNETIC CORE, 15nH, -5%/+5%, 0.25A, -55DEGC/+125DEGC, 0201, SMD; ALT_SYMBOLS: INDC0603X33A2L,INDC0603X33A2M; Additional Datasheet URL: https://search.murata.co.jp/Ceramy/image/img/P02/JELF243C-0015.pdf; Datasheet URL: https://www.murata.com/-/media/webrenewal/support/library/catalog/products/inductor/chip/o05e.ashx?la=en-gb; Frequency: 2600MHz; Mass: 0.0002g; Maximum Operating Temperature: +125DEGC; Maximum Tolerance: +5%; Minimum Operating Temperature: -55DEGC; Minimum Tolerance: -5%; Mounting Type: SMD; NOTEfied URL: https://notefied-dynamic-precision.com/NOTEfiedWebInterface/part/show?partNumber=03-08091; PCB Package: 0201; Packing Size: 15000; Packing Type: Tape & Reel; Part Number: 03-08091; Part Type: Inductor|RF|CHIP|0201; REACH/SVHC Compliance: Compliant; REACH/SVHC Details: SVHC List Version Jul 16, 2019; REACH/SVHC Source: REACH Declaration; REACH/SVHC Status: Unaffected; ROHS: Compliant; Resistance: 0.7; Revision: R003; Status: Released; Texas Part Status: Under Review; Type: Inductor; Vendor: MURATA; Vendor Part Number: LQP03TN15NJ02D; Vendor Part Status: Active
L12 = INDUCTOR: INDUCTOR, RF, CHIP, NON-MAGNETIC CORE, 2.8nH, -0.1nH/+0.1nH, 0.5A, -55DEGC/+125DEGC, 0201, SMD; ALT_SYMBOLS: INDC0603X33A2L,INDC0603X33A2M; Additional Datasheet URL: https://search.murata.co.jp/Ceramy/image/img/P02/JELF243C-0015.pdf; Country of Origin: Missing Info; Datasheet URL: https://www.murata.com/-/media/webrenewal/support/library/catalog/products/inductor/chip/o05e.ashx?la=en-gb; Frequency: 9.5GHz; Mass: 0.0002g; Maximum Operating Temperature: +125DEGC; Maximum Tolerance: +0.1nH; Minimum Operating Temperature: -55DEGC; Minimum Tolerance: -0.1nH; Mounting Type: SMD; NOTEfied URL: https://notefied-dynamic-precision.com/NOTEfiedWebInterface/part/show?partNumber=03-06931; PCB Package: 0201; Packing Size: 50000; Packing Type: Tape & Reel; Part Number: 03-06931; Part Type: Inductor|RF|CHIP|0201; ROHS: Compliant; Resistance: 0.2; Revision: R015; Status: Released; Texas Part Status: Under Review; Type: Inductor; Vendor: MURATA; Vendor Part Number: LQP03TN2N8B02J; Vendor Part Status: Active
L31 = INDUCTOR: INDUCTOR, RF, CHIP, NON-MAGNETIC CORE, 150nH, -5%/+5%, 0.08A, -55DEGC/+125DEGC, 0201, SMD; ALT_SYMBOLS: INDC0603X33A2L,INDC0603X33A2M; Additional Datasheet URL: https://search.murata.co.jp/Ceramy/image/img/P02/JELF243C-0015.pdf; Datasheet URL: https://www.murata.com/-/media/webrenewal/support/library/catalog/products/inductor/chip/o05e.ashx?la=en-gb; Frequency: 650MHz; Mass: 0.0002g; Maximum Operating Temperature: +125DEGC; Maximum Tolerance: +5%; Minimum Operating Temperature: -55DEGC; Minimum Tolerance: -5%; Mounting Type: SMD; NOTEfied URL: https://notefied-dynamic-precision.com/NOTEfiedWebInterface/part/show?partNumber=03-08114; PCB Package: 0201; Packing Size: 15000; Packing Type: Tape & Reel; Part Number: 03-08114; Part Type: Inductor|RF|CHIP|0201; REACH/SVHC Compliance: Compliant; REACH/SVHC Details: SVHC List Version Jul 16, 2019; REACH/SVHC Source: REACH Declaration; REACH/SVHC Status: Unaffected; ROHS: Compliant; Resistance: 9; Revision: R003; Status: Released; Texas Part Status: Under Review; Type: Inductor; Vendor: MURATA; Vendor Part Number: LQP03TNR15J02D; Vendor Part Status: Active
L32 = INDUCTOR: INDUCTOR, RF, CHIP, NON-MAGNETIC CORE, 47nH, -5%/+5%, 0.21A, -55DEGC/+125DEGC, 0402, SMD; Additional Datasheet URL: https://search.murata.co.jp/Ceramy/image/img/P02/JELF243A-0050.pdf; Budgetary Price: 0.048 USD; Country of Origin: Japan,Singapore; Datasheet URL: https://www.murata.com/-/media/webrenewal/support/library/catalog/products/inductor/chip/o05e.ashx?la=en-gb; Lead Time: 8; Mass: 0.0008g; Maximum Operating Temperature: +125DEGC; Maximum Tolerance: +5%; Minimum Operating Temperature: -55DEGC; Minimum Tolerance: -5%; Mounting Type: SMD; NOTEfied URL: https://notefied-dynamic-precision.com/NOTEfiedWebInterface/part/show?partNumber=03-07897; PCB Package: 0402; Packing Size: 10000; Packing Type: Tape & Reel; Part Number: 03-07897; Part Type: Inductor|RF|CHIP|0402; REACH/SVHC Compliance: Compliant; REACH/SVHC Details: SVHC List Version Jan 15, 2018; REACH/SVHC Source: REACH Declaration; REACH/SVHC Status: Unaffected; ROHS: Compliant; Resistance: 1.08; Revision: R009; Status: Released; Texas Part Status: Under Review; Type: Inductor; Vendor: MURATA; Vendor Part Number: LQW15AN47NJ00D; Vendor Part Status: Active
L33 = INDUCTOR: INDUCTOR, RF, CHIP, NON-MAGNETIC CORE, 68nH, -5%/+5%, 0.14A, -55DEGC/+125DEGC, 0402, SMD; ALT_SYMBOLS: INDC1005X60A2L,INDC1005X60A2M; Additional Datasheet URL: https://search.murata.co.jp/Ceramy/image/img/P02/JELF243A-0050.pdf; Budgetary Price: 0.048 USD; Country of Origin: Japan,Singapore; Datasheet URL: https://www.murata.com/-/media/webrenewal/support/library/catalog/products/inductor/chip/o05e.ashx?la=en-gb; FPLIST: INDC1005X60A2N,INDC1005X60B2N; Frequency: 2.5GHz; Lead Time: 8; Mass: 0.0008g; Maximum Operating Temperature: +125DEGC; Maximum Tolerance: +5%; Minimum Operating Temperature: -55DEGC; Minimum Tolerance: -5%; Mounting Type: SMD; NOTEfied URL: https://notefied-dynamic-precision.com/NOTEfiedWebInterface/part/show?partNumber=03-06597; PCB Package: 0402; Packing Size: 10000; Packing Type: Tape & Reel; Part Number: 03-06597; Part Type: Inductor|RF|CHIP|0402; REACH/SVHC Compliance: Compliant; REACH/SVHC Details: SVHC List Version Jul 7, 2017; REACH/SVHC Source: REACH Declaration; REACH/SVHC Status: Unaffected; ROHS: Compliant; Resistance: 1.96; Revision: R022; Status: Released; Texas Part Status: Under Review; Type: Inductor; Vendor: MURATA; Vendor Part Number: LQW15AN68NJ00D; Vendor Part Status: Active
L331 = INDUCTOR: INDUCTOR, STANDARD, FERRITE CORE, 6.8uH, -20%/+20%, 0.11A, -55DEGC/+125DEGC, 0805, SMD; ALT_SYMBOLS: INDC2012X150A2L,INDC2012X150A2M; Additional Datasheet URL: https://product.tdk.com/en/search/inductor/inductor/smd/info?part_no=MLZ2012N6R8LT000; AutoDoc File: https://notefied-dynamic-precision.com/DB/Apps/Desktop/Item/Object.aspx?id=102853; BU Name: DYNAMIC PRECISION GDANSK; Budget Currency: EUR; Budget Price: 0.059; Budgetary Price: 0.045 USD; Client Status: UNDER_REVIEW; Core Material: FERRITE; Country of Origin: Missing Info; Datasheet URL: http://product.tdk.com/info/en/catalog/datasheets/inductor_commercial_decoupling_mlz2012_en.pdf; Datasheet URL 1: https://product.tdk.com/info/en/catalog/datasheets/inductor_commercial_decoupling_mlz2012_en.pdf; Datasheet URL 2: N/A; Lead Time: 10; MPN: MLZ2012N6R8LT000; MPN Status: ACTIVE; Manufacturer: TDK; Mass: 0.01g; Max Oper Temp: +125DEGC; Max Tol: +20%; Maximum Operating Temperature: +125DEGC; Maximum Tolerance: +20%; Min Oper Temp: -55DEGC; Min Tol: -20%; Minimum Operating Temperature: -55DEGC; Minimum Tolerance: -20%; Mounting Type: SMD; NOTE Status: PREFERRED; NOTEfied URL: https://notefied-dynamic-precision.com/NOTEfiedWebInterface/part/show?partNumber=03-07266; Old Footprint: INDC2012X150N; PCB Package: 0805; Packing Size: 4000; Packing Type: Tape & Reel; Part Number: 03-07266; Part Type: Inductor|STANDARD|CHIP|0805; REACH/SVHC Compliance: Compliant; REACH/SVHC Details: SVHC List Version Jan 12, 2017; REACH/SVHC Source: REACH Declaration; REACH/SVHC Status: Unaffected; REACH/SVHC_COMPLIANCE: COMPLIANT; REACH/SVHC_DETAILS: SVHC LIST VERSION Dec 17, 2015; REACH/SVHC_SOURCE: REACH DECLARATION; REACH/SVHC_STATUS: UNAFFECTED; ROHS: Compliant; Resistance: 0.25; Revision: R016; RoHS Status: ROHS_COMPLIANT; Rtd Current: 1.1A; Status: Released; Texas Part Status: Under Review; Type: Inductor; Vendor: TDK; Vendor Part Number: MLZ2012N6R8LT000; Vendor Part Status: Active; WEIGHT: 0.01g
L338 = INDUCTOR: INDUCTOR, RF, CHIP, NON-MAGNETIC CORE, 82nH, -5%/+5%, 0.13A, -55DEGC/+125DEGC, 0402, SMD; ALT_SYMBOLS: INDC1005X60A2L,INDC1005X60A2M; Additional Datasheet URL: https://search.murata.co.jp/Ceramy/image/img/P02/JELF243A-0050.pdf; Budgetary Price: 0.048 USD; Country of Origin: Japan,Singapore; Datasheet URL: https://www.murata.com/-/media/webrenewal/support/library/catalog/products/inductor/chip/o05e.ashx?la=en-gb; FPLIST: INDC1005X60A2N,INDC1005X60B2N; Frequency: 2.3GHz; Lead Time: 8; Mass: 0.0008g; Maximum Operating Temperature: +125DEGC; Maximum Tolerance: +5%; Minimum Operating Temperature: -55DEGC; Minimum Tolerance: -5%; Mounting Type: SMD; NOTEfied URL: https://notefied-dynamic-precision.com/NOTEfiedWebInterface/part/show?partNumber=03-06598; PCB Package: 0402; Packing Size: 10000; Packing Type: Tape & Reel; Part Number: 03-06598; Part Type: Inductor|RF|CHIP|0402; REACH/SVHC Compliance: Compliant; REACH/SVHC Details: SVHC List Version Jul 7, 2017; REACH/SVHC Source: REACH Declaration; REACH/SVHC Status: Unaffected; ROHS: Compliant; Resistance: 2.24; Revision: R022; Status: Released; Texas Part Status: Under Review; Type: Inductor; Vendor: MURATA; Vendor Part Number: LQW15AN82NJ00D; Vendor Part Status: Active
P1 P2 = CONN_HEADER_2X10_P_S: CONNECTOR, HEADER, FEMALE, STRAIGHT, 2 ROWS, 20 PINS, PITCH 1.27mm, SMD; ALT_SYMBOLS: SAMTEC_SFM11002AL,SAMTEC_SFM11002AM; Additional Datasheet URL: http://suddendocs.samtec.com/prints/sfm-1xx-xx-xxx-d-xxx-mkt.pdf; Alt IPC Footprints: SAMTEC_SFM11002AL,SAMTEC_SFM11002AM; AutoDoc File: https://notefied-dynamic-precision.com/DB/Apps/Desktop/Item/Object.aspx?id=85603; BU Name: TEXAS INSTRUMENTS NORWAY; Budget Currency: USD; Budget Price: 3.180; Budgetary Price: 5.3504 USD; CLASS: IO; Client Status: UNDER_REVIEW; Country of Origin: China,Costa Rica,Malaysia,Singapore,United States; Datasheet URL: http://suddendocs.samtec.com/catalog_english/sfm.pdf; Datasheet URL 1: http://suddendocs.samtec.com/catalog_english/sfm.pdf; Datasheet URL 2: http://suddendocs.samtec.com/prints/sfm-1xx-xx-xxx-d-xxx-mkt.pdf; Lead Time: 4; MPN: SFM-110-02-SM-D-A-K-TR; MPN Status: ACTIVE; Manufacturer: SAMTEC; Mass: 0.30875g; Max Oper Temp: +125DEGC; Maximum Operating Temperature: +125DEGC; Min Oper Temp: -55DEGC; Minimum Operating Temperature: -55DEGC; Mounting Type: SMD; NOTE Status: PREFERRED; NOTEfied URL: https://notefied-dynamic-precision.com/NOTEfiedWebInterface/part/show?partNumber=06-02251; No Of Pos: 20; No Of Rows: 2; Number of Positions: 20; Number of Rows: 2; Packing Size: 725; Packing Type: Tape & Reel; Part Number: 06-02251; Part Type: Connector|HEADER|STANDARD; Pitch: 1.27mm; REACH/SVHC Compliance: Compliant; REACH/SVHC Details: SVHC List Version Jan 12, 2017; REACH/SVHC Source: Material Declaration; REACH/SVHC Status: Unaffected; ROHS: Compliant; Revision: R014; RoHS Status: ROHS_COMPLIANT; Status: Released; Texas Part Status: Under Review; Type: Connector; Vendor: SAMTEC; Vendor Part Number: SFM-110-02-SM-D-A-K-TR; Vendor Part Status: Active; Weight: 0.30875g
R351 = RESISTOR: RESISTOR, THICK FILM, 100k, -5%/+5%, 0.063W, 50V, -55DEGC/+155DEGC, 0402, SMD; Additional Datasheet URL: N/A; AutoDoc File: https://notefied-dynamic-precision.com/DB/Apps/Desktop/Item/Object.aspx?id=114565; BU Name: TEXAS INSTRUMENTS NORWAY; Budget Currency: EUR; Budget Price: 0.014; Budgetary Price: 0.014 EUR; Client Status: UNDER_REVIEW; Country of Origin: United States; Datasheet URL: http://www.vishay.com/docs/20035/dcrcwe3.pdf; Datasheet URL 1: http://www.vishay.com/docs/20035/dcrcwe3.pdf; Datasheet URL 2: N/A; Definied Quality: INDUSTRIAL; Esd Level: N/A; Exclusive for Customers: TEXAS INSTRUMENTS NORWAY; Lead Time: 18; LifeCycle Status: ACTIVE; MPN: RESISTOR_0402_100k_+/-1%_50V_0.063W_M_+/-100PPM; MPN Status: ACTIVE; MSL: N/A; MTBF: N/A; MTBF Standard: N/A; Manufacturer: MANUFACTURER SELECTION; Mass: 0.00065g; Max Oper Temp: +155DEGC; Max TC: +200PPM/DEGC; Max Tol: +5%; Maximum Operating Temperature: +155DEGC; Maximum Temperature Coefficient: +200PPM/DEGC; Maximum Tolerance: +5%; Min Oper Temp: -55DEGC; Min TC: -200PPM/DEGC; Min Tol: -5%; Minimum Operating Temperature: -55DEGC; Minimum Temperature Coeficient: -200PPM/DEGC; Minimum Tolerance: -5%; Mounting Type: SMD; NOTE Status: PREFERRED; NOTEfied URL: https://notefied-dynamic-precision.com/NOTEfiedWebInterface/part/show?partNumber=01-22492; Notes: Standard item: Duplicate Reason: custom footprint for TEXAS INSTRUMENTS NORWAY.; Old Footprint: RESC1005X40N; PCB Package: 0402; Packing Size: 10000; Packing Type: Tape & Reel; Part Number: 01-22492; Part Type: Resistor|0402|STANDARD; REACH/SVHC Compliance: Compliant; REACH/SVHC Details: SVHC List Version Jun 20, 2016; REACH/SVHC Source: Material Declaration; REACH/SVHC Status: Unaffected; REACH/SVHC_COMPLIANCE: COMPLIANT; REACH/SVHC_DETAILS: SVHC LIST VERSION Jun 20, 2016; REACH/SVHC_SOURCE: MATERIAL DECLARATION; REACH/SVHC_STATUS: UNAFFECTED; ROHS: Exempt; Rated Current: N/A; Rated Power: 0.063W; Rated Voltage: 50V; Resistor Type: THICK FILM; Revision: R017; RoHS Status: ROHS_COMPLIANT; Rtd Current: N/A; Rtd Power: 0.063W; Rtd Voltage: 50V; Status: Released; Texas Part Status: Under Review; Type: Resistor; Vendor: VISHAY; Vendor Part Number: CRCW0402100KJNED; Vendor Part Status: Active; WEIGHT: 0.00065g
U1 = IC_RF_CC1352R_VQFN48: IC, MICROCONTROLLER, TEXAS INSTRUMENTS, ARM CORTEX M4F, HIGH-PERFORMANCE DUAL-BAND WIRELESS MCU, 1.8V TO 3.8V, VQFN48-EP, SMD; ALT_SYMBOLS: QFNFC50P700X700X100-49A2L,QFNFC50P700X700X100-49A2M; Additional Datasheet URL: http://www.ti.com/lit/ml/mpqf123f/mpqf123f.pdf; Datasheet URL: https://www.ti.com/lit/ds/symlink/cc1352r.pdf; Frequency: 48MHz; Mass: 0.1465g; Maximum Operating Temperature: +85DEGC; Minimum Operating Temperature: -40DEGC; Mounting Type: SMD; NOTEfied URL: https://notefied-dynamic-precision.com/NOTEfiedWebInterface/part/show?partNumber=18-33499; PCB Package: VQFN48-EP; Packing Size: 250; Packing Type: Tape & Reel; Part Number: 18-33499; Part Type: IC|MICROCONTROLLER|TEXAS INSTRUMENTS; REACH/SVHC Compliance: Compliant; REACH/SVHC Details: SVHC List Version Jan 15, 2019; REACH/SVHC Source: REACH Declaration; REACH/SVHC Status: Unaffected; ROHS: Compliant; Rated Voltage: 1.8V TO 3.8V; Revision: R023; Status: Released; Texas Part Status: Under Review; Type: IC; Vendor: TEXAS INSTRUMENTS; Vendor Part Number: CC1352R1F3RGZT; Vendor Part Status: Active
Y1 = CRYSTAL: CRYSTAL, RESONATOR, 32.768kHz, -40DEGC/+85DEGC, SMD; ALT_SYMBOLS: XTAL_FC135_A2L,XTAL_FC135_A2M; Additional Datasheet URL: http://www5.epsondevice.com/en/products/crystal_unit/fc135.html; AutoDoc File: https://notefied-dynamic-precision.com/DB/Apps/Desktop/Item/Object.aspx?id=91966; BU Name: DYNAMIC PRECISION GDANSK; Budget Currency: EUR; Budget Price: 0.61; Budgetary Price: 0.238 EUR; CLASS: IC; Capacitance: 7pF; Client Status: UNDER_REVIEW; Country of Origin: Japan; Datasheet URL: https://support.epson.biz/td/api/doc_check.php?dl=brief_FC-135&lang=en; Datasheet URL 1: https://support.epson.biz/td/api/doc_check.php?mode=dl&lang=en&Parts=FC-135; Datasheet URL 2: http://www5.epsondevice.com/en/products/khz_range/fc135.html; Definied Quality: INDUSTRIAL; Esd Level: N/A; Lead Time: 13; MPN: FC-135 32.7680KA-AG0; MPN Status: ACTIVE; MSL: N/A; MTBF: N/A; MTBF Standard: N/A; Manufacturer: EPSON; Mass: 0.016g; Max Oper Temp: +85DEGC; Max TC: N/A; Max Tol: +20PPM; Maximum Operating Temperature: +85DEGC; Maximum Stability: N/A; Maximum Tolerance: +20PPM; Min Oper Temp: -40DEGC; Min TC: N/A; Min Tol: -20PPM; Minimum Operating Temperature: -40DEGC; Minimum Stability: N/A; Minimum Tolerance: -20PPM; Mounting Type: SMD; NOTE Status: PREFERRED; NOTEfied URL: https://notefied-dynamic-precision.com/NOTEfiedWebInterface/part/show?partNumber=12-00546; Notes: This device contains Lead titanium trioxide, CAS No. 12060-00-3, which exceeds the 0.1% SVHC limit. / Alias p/n:Q13FC13500002; Old Footprint: XTAL_FC-135N; Packing Size: 1000; Packing Type: Tape & Reel; Part Number: 12-00546; Part Type: Crystal|RESONATOR; REACH/SVHC Compliance: Non-Compliant; REACH/SVHC Details: SVHC List Version Jan 15, 2019; REACH/SVHC Source: REACH Declaration; REACH/SVHC Status: Affected; REACH/SVHC_COMPLIANCE: COMPLIANT; REACH/SVHC_DETAILS: SVHC LIST VERSION Dec 17, 2015; REACH/SVHC_SOURCE: REACH DECLARATION; REACH/SVHC_STATUS: UNAFFECTED; ROHS: Exempt; Rated Voltage: N/A; Revision: R021; RoHS Status: ROHS_COMPLIANT_WITH_EXEMPTION; Rtd Voltage: N/A; Status: Released; Texas Part Status: Under Review; Type: Crystal; Vendor: EPSON; Vendor Part Number: FC-135 32.7680KA-AG0; Vendor Part Status: Active; WEIGHT: N/A
Y2 = XTAL_4PINS_1_3: CRYSTAL, RESONATOR, 48MHz, -85PPM/+85PPM, -40DEGC/+125DEGC, SMD; ALT_SYMBOLS: OSCCC200X160X50-4B2L,OSCCC200X160X50-4B2M; Additional Datasheet URL: https://www.ndk.com/en/products/search/crystal/1190853_1494.html; AutoDoc File: https://notefied-dynamic-precision.com/DB/Apps/Desktop/Item/Object.aspx?id=116070; BU Name: TEXAS INSTRUMENTS NORWAY; Capacitance: 7pF; Client Status: UNDER_REVIEW; Datasheet URL: https://www.ndk.com/images/products/catalog/c_NX2016SA-2_e.pdf; Datasheet URL 1: https://notefied-dynamic-precision.com/db/Apps/OpenDocument.aspx?obj=5&docid=247737; Datasheet URL 2: http://www.ndk.com/images/products/catalog/c_NX2016SA_e.pdf; Exclusive for Customers: TEXAS INSTRUMENTS NORWAY; Mass: N/A; Max Oper Temp: +125DEGC; Max TC: +85PPM; Max Tol: +10PPM; Maximum Operating Temperature: +125DEGC; Maximum Stability: +85PPM; Maximum Tolerance: +10PPM; Min Oper Temp: -40DEGC; Min TC: -85PPM; Min Tol: -10PPM; Minimum Operating Temperature: -40DEGC; Minimum Stability: -85PPM; Minimum Tolerance: -10PPM; Mounting Type: SMD; NOTEfied URL: https://notefied-dynamic-precision.com/NOTEfiedWebInterface/part/show?partNumber=12-01232; Notes: Custom item:Documentation specified for the client; Packing Size: 3000; Packing Type: Tape & Reel; Part Number: 12-01232; Part Type: Crystal|RESONATOR; REACH/SVHC Compliance: Compliant; REACH/SVHC Details: SVHC List Version Jun 20, 2016; REACH/SVHC Source: REACH Declaration; REACH/SVHC Status: Unaffected; ROHS: Compliant; Rated Voltage: N/A; Revision: R018; RoHS Status: ROHS_COMPLIANT; Rtd Voltage: N/A; Status: Released; Texas Part Status: Under Review; Type: Crystal; Vendor: NIHON DEMPA KOGYO; Vendor Part Number: NX2016SA 48.000MHz EXS00A-CS05517; Vendor Part Status: Active
FIDU1-FIDU6 = FIDMARK: NON COMPONENT, FIDUCIAL MARK, ROUND 1mm, SMD; Additional Datasheet URL: N/A; AutoDoc File: https://notefied-dynamic-precision.com/DB/Apps/Desktop/Item/Object.aspx?id=74548; BU Name: DYNAMIC PRECISION GDANSK; CLASS: IO; Country of Origin: Missing Info; Datasheet URL: N/A; Mass: N/A; Mounting Type: SMD; NOTEfied URL: https://notefied-dynamic-precision.com/NOTEfiedWebInterface/part/show?partNumber=19-00111; Old Footprint: FID100X115; Packing Size: N/A; Packing Type: Missing Info; Part Number: 19-00111; Part Type: Non Component|FIDUCIAL; ROHS: Compliant; Revision: R016; Status: Released; Type: Non Component; Vendor: NON_COMPONENT; Vendor Part Number: FIDUCIAL_1mm; Vendor Part Status: Active
LBL1 = LABEL_Pb-free_V1: NON COMPONENT, LABEL, PB-FREE, 8mm; Additional Datasheet URL: N/A; AutoDoc File: https://notefied-dynamic-precision.com/DB/Apps/Desktop/Item/Object.aspx?id=57438; BU Name: DYNAMIC PRECISION GDANSK; Country of Origin: Missing Info; Datasheet URL: N/A; Mass: N/A; Mounting Type: NOT APPLY; NOTEfied URL: https://notefied-dynamic-precision.com/NOTEfiedWebInterface/part/show?partNumber=19-00159; Packing Size: N/A; Packing Type: Missing Info; Part Number: 19-00159; Part Type: Non Component|LABEL; ROHS: Missing Info; Revision: R012; Status: Released; Type: Non Component; Vendor: NON_COMPONENT; Vendor Part Status: Active
LBL2 = TI_LOGO_V1: NON COMPONENT, LABEL, TEXAS INSTRUMENTS LOGO; Additional Datasheet URL: N/A; AutoDoc File: https://notefied-dynamic-precision.com/DB/Apps/Desktop/Item/Object.aspx?id=87770; BU Name: TEXAS INSTRUMENTS NORWAY; Country of Origin: Missing Info; Datasheet URL: N/A; Exclusive for Customers: TEXAS INSTRUMENTS NORWAY; Mass: N/A; Mounting Type: NOT APPLY; NOTEfied URL: https://notefied-dynamic-precision.com/NOTEfiedWebInterface/part/show?partNumber=19-00350; Notes: Custom Item; Packing Size: N/A; Packing Type: Missing Info; Part Number: 19-00350; Part Type: Non Component|LABEL; ROHS: Missing Info; Revision: R015; Status: Released; Texas Part Status: Under Review; Type: Non Component; Vendor: NON_COMPONENT; Vendor Part Status: Active
R352-R355 = RESISTOR: RESISTOR, THICK FILM, 0, 0R/+0.05R, 0.05W, 1A, -55DEGC/+155DEGC, 0201, SMD; ALT_SYMBOLS: RESC0603X35B2L,RESC0603X35B2M; Additional Datasheet URL: N/A; Budgetary Price: 0.009 EUR; Country of Origin: Israel; Datasheet URL: http://www.vishay.com/docs/20052/crcw0201e3.pdf; Lead Time: 10; Mass: 0.00017g; Maximum Operating Temperature: +155DEGC; Maximum Temperature Coefficient: N/A; Maximum Tolerance: +0.05R; Minimum Operating Temperature: -55DEGC; Minimum Temperature Coeficient: N/A; Minimum Tolerance: 0R; Mounting Type: SMD; NOTEfied URL: https://notefied-dynamic-precision.com/NOTEfiedWebInterface/part/show?partNumber=01-04043; PCB Package: 0201; Packing Size: 10000; Packing Type: Tape & Reel; Part Number: 01-04043; Part Type: Resistor|0201|JUMPER; REACH/SVHC Compliance: Compliant; REACH/SVHC Details: SVHC List Version Dec 17, 2015; REACH/SVHC Source: Material Declaration; REACH/SVHC Status: Unaffected; ROHS: Exempt; Rated Current: 1A; Rated Power: 0.05W; Rated Voltage: N/A; Resistor Type: THICK FILM; Revision: R020; Status: Released; Type: Resistor; Vendor: VISHAY; Vendor Part Number: CRCW02010000Z0ED; Vendor Part Status: Active

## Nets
GND: C1.2 C11.2 C12.2 C31.1 C32.2 C33.1 C81.2 C91.2 C131.2 C221.2 C231.2 C331.2 C341.2 C342.2 C351.2 C441.2 C451.2 C461.2 C471.2 C481.2 C503.1 C505.1 C506.1 J1.2 J1.3 J1.4 J1.5 J2.2 J2.3 J2.4 J2.5 J3.2 J3.3 J3.4 J3.5 P1.1 P1.19 P2.2 P2.20 R352.1 R353.1 R354.1 R355.1 U1.49(EGP) Y2.2(GND) Y2.4(GND)
VDD_EB: FL1.2 P2.7 P2.9
VDDR: C331.1 C451.1 C481.1 L331.2 U1.45(VDDR) U1.48(VDDR_RF)
VDDS: C1.1 C131.1 C221.1 C341.1 C342.1 C441.1 FL1.1 R351.2 U1.13(VDDS2) U1.22(VDDS3) U1.34(VDDS_DCDC) U1.44(VDDS)
DCDC_SW: L331.1 U1.33(DCDC_SW)
DIO_3: P1.9 U1.8(DIO_3)
DIO_4: P1.11 U1.9(DIO_4)
DIO_5: P1.13 U1.10(DIO_5)
DIO_6: P1.4 U1.11(DIO_6)
DIO_7: P1.2 U1.12(DIO_7)
DIO_8: P1.20 U1.14(DIO_8)
DIO_9: P1.18 U1.15(DIO_9)
DIO_10: P1.16 U1.16(DIO_10)
DIO_11: P1.14 U1.17(DIO_11)
DIO_12: P1.12 U1.18(DIO_12)
DIO_13: P1.15 U1.19(DIO_13)
DIO_14: P1.17 U1.20(DIO_14)
DIO_15: P1.6 U1.21(DIO_15)
DIO_16 / JTAG TDO: P2.19 U1.26(DIO_16)
DIO_17 / JTAG TDI: P2.17 U1.27(DIO_17)
DIO_18: P1.8 U1.28(DIO_18)
DIO_19: P1.10 U1.29(DIO_19)
DIO_20: P2.8 U1.30(DIO_20)
DIO_21: P2.18 U1.31(DIO_21)
DIO_22: P1.3 U1.32(DIO_22)
DIO_23: P2.5 U1.36(DIO_23)
DIO_24: P2.10 U1.37(DIO_24)
DIO_25: P2.11 U1.38(DIO_25)
DIO_26: P2.6 U1.39(DIO_26)
DIO_27: P2.13 U1.40(DIO_27)
DIO_28: P2.16 U1.41(DIO_28)
DIO_29: P2.14 U1.42(DIO_29)
DIO_30: P2.12 U1.43(DIO_30)
JTAG_TCK: P2.1 U1.25(JTAG_TCKC)
JTAG_TMS: P2.4 U1.24(JTAG_TMSC)
nRESET: C351.1 P2.15 R351.1 U1.35(RESET_N)
RX_TX: C503.2 L31.2 U1.5(RX_TX)
N485533: C36.2 J1.1
N485707: C91.1 U1.7(X32K_Q2) Y1.2
N501979: C461.1 U1.46(X48M_N) Y2.3
N512564: C15.2 J2.1
N567744: L11.2 U1.2(2_4_GHZ_RF_N)
N567770: C11.1 L11.1 L12.1 U1.1(2_4_GHZ_RF_P)
N3412703: C505.2 L31.1 L338.1 U1.3(SUB-1_GHZ_RF_P)
N3413556: C31.2 L32.1 U1.4(SUB-1_GHZ_RF_N)
N3413564: C32.1 L32.2 L33.1
N3413576: C33.2 C36.1 L33.2
N3415261: C504.1 J3.1
N3415578: C12.1 C15.1 L12.2
N3417420: C504.2 C506.2 L338.2
N3424378: C471.1 U1.47(X48M_P) Y2.1
N3424914: C231.1 U1.23(DCOUPL)
N3425185: C81.1 U1.6(X32K_Q1) Y1.1
N3440275: R352.2 R353.2
N3440401: R354.2 R355.2

Not connected (* = marked no-connect by the designer): FIDU1 1*; FIDU2 1*; FIDU3 1*; FIDU4 1*; FIDU5 1*; FIDU6 1*; P1 5* 7*; P2 3*

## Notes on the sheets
sheet 1
- For trace impedance measurement.
sheet 2
- VDDS Decoupling Capacitors
- VDDR Decoupling Capacitors
- Pin 13
- Pin 22
- Pin 44
- Pin 34
- Pin 45
- Pin 48
- Place L331 and C331 close to pin 33.
  Low inductance ground for C331
- 2.4GHz RF
- 169MHz RF RX input
- 169MHz RF TX output
- EM connector 1
- EM connector 2
sheet 3
- R 1.0.0
  --------------------------------------------------------------------------------------------
  -Initial release revision.
  ---------------------------------------------------------------------------------------------
  R B0
  ---------------------------------------------------------------------------------------------
  - Updating CC1352R to CC1352R13RGZ
  - Changing C81 from GRM1555C1H120JA01 (0402, NRND) to GRT033C1H120JA02 (0201, Active)
  - Changing C91 from GRM1555C1H120JA01 (0402, NRND) to GRT033C1H120JA02 (0201, Active)
  - Changing C15,C31,C33,C81,C91,C505,C506 12pF from GRT0335C1H120JA02D to GRM0335C1E120JA01D
  - Added option for external XOSCHF load caps (C461 and C471)
  R C0
  ---------------------------------------------------------------------------------------------
  - Changing design name from CC1352EM-XS169-XS24 to CC1352REM-XS169-XS24
